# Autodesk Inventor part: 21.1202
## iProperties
Created: 2006-02
Part Number: 21.1202
Material: Steel, Mild
Description: M8 x 20 SHCS
Document SubType Name: Modeling
Standard: DIN 7984
Designer: Andy Moles
Standards Organization: DIN
Language: en-US
Size Designation: M8 x 20
Categories: <MemberInstance><Categories><Category DisplayName="Fasteners" InternalName="e4da775c-781d-43d5-af7c-5136215cf5a6" Mnemonic="FSTN"><Category DisplayName="Bolts"
Mass: 12.263 g
Surface Area: 10.1767 cm^2
Volume: 1.56018 cm^3
Density: 7.86 g/cm^3
Vendor: S
Author: Andy Moles
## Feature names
1. Body [Revolution]
2. Slot [Extrusion]
3. Fillet1
4. Chamfer1
